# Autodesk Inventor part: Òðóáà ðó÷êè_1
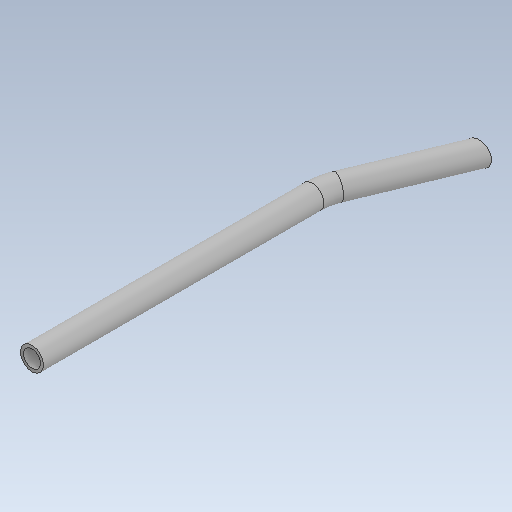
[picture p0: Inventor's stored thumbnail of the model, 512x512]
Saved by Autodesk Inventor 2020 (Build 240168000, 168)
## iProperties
Created: 1900-01
Part Number: Òðóáà ðó÷êè_1
Material: Générique
Document SubType Name: Modeling
Designer: bruno
Density: 1 g/cm^3
Appearance: Par défaut
Author: bruno
Revision Number: ANYUNSPECIFIED
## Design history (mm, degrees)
feature "Base1"
node "Solide1"
